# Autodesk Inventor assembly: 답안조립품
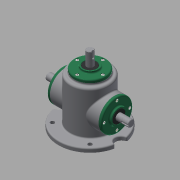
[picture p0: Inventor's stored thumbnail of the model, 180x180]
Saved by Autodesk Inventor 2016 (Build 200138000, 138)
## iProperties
Created: 2018-04
Part Number: 답안조립품
Material: 일반
Document SubType Name: Assembly
Designer: 605-08
Author: 605-08
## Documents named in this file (16)
- C:\Users\605-08\Desktop\480407V1004\답안조립품.iam
- C:\Users\605-08\Desktop\480407V1004\본체.ipt
- C:\Users\605-08\Desktop\480407V1004\커버.ipt
- C:\Users\605-08\Desktop\480407V1004\오일 실.ipt
- 오일 실.ipt
- C:\Users\605-08\Desktop\480407V1004\베어링 6203.ipt
- C:\Users\605-08\Desktop\480407V1004\메인 축.ipt
- 메인 축.ipt
- C:\Users\605-08\Desktop\480407V1004\서브 축.ipt
- 서브 축.ipt
- C:\Users\605-08\Desktop\480407V1004\메인 베벨기어.ipt
- C:\Users\605-08\Desktop\480407V1004\키 5x5.ipt
- C:\Users\605-08\Desktop\480407V1004\서브 베벨기어.ipt
- C:\Users\605-08\Desktop\480407V1004\키 4x4.ipt
- C:\Users\605-08\Desktop\480407V1004\볼트 M4.ipt
- 볼트 M4.ipt
